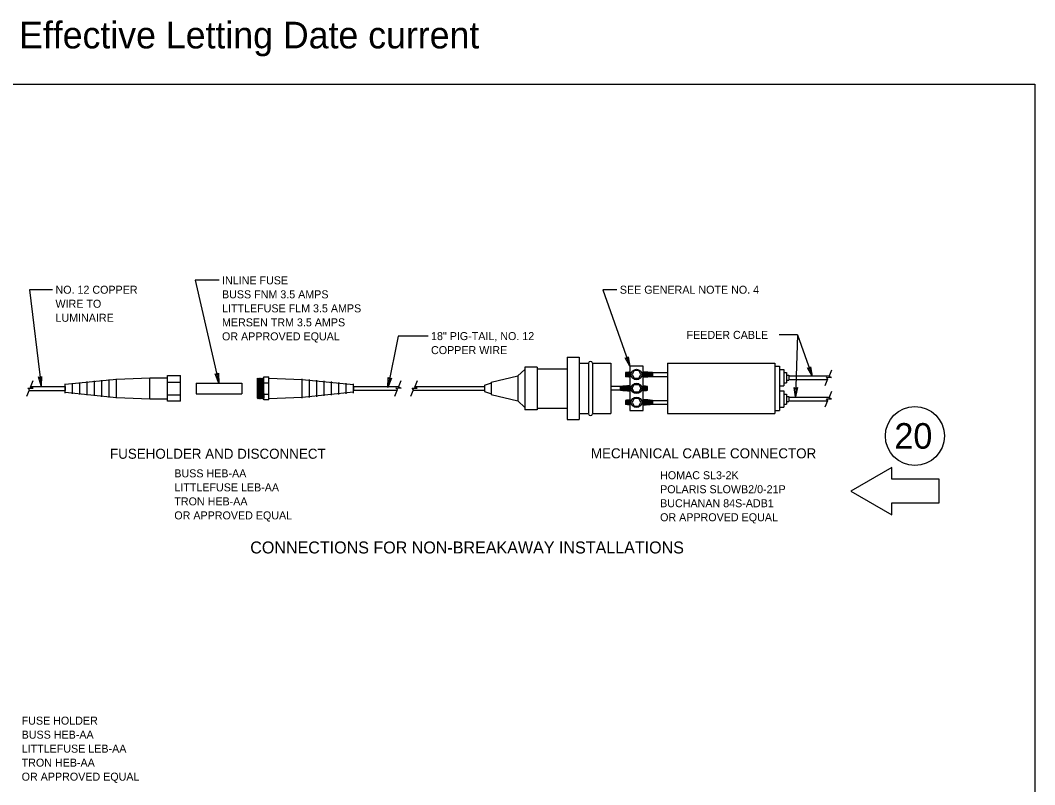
# Model space of a CAD drawing. Extents: x 99981 to 128681, y 99783 to 102182.
# Drawn here: x 127161 to 128681, y 101036 to 102182 of the extents above; entities that cross this region are included whole.
import ezdxf

# ---------------------------------------------------------------- set-up
doc = ezdxf.new("R2010")
doc.units = 0
for name, color, linetype in [('Default', 7, 'Continuous'), ('Level 1', 7, 'Continuous'), ('RD Lighting', 7, 'Continuous'), ('RD Standard Plans Active', 7, 'Continuous')]:
    doc.layers.add(name, color=color, linetype=linetype)

msp = doc.modelspace()

# ---------------------------------------------------------------- linework, layer by layer
at = {"layer": 'Default'}
msp.add_lwpolyline([(125481.4, 102086.3), (128681.1, 102086.3), (128681.1, 99886.7), (125481.4, 99886.7)], close=True, dxfattribs=at)
at = {"layer": 'Level 1'}
for p, q in [((127422.6, 101792.3), (127458.4, 101638.1)), ((127458.5, 101792.3), (127422.6, 101792.3)), ((127208.9, 101778.2), (127174.4, 101778.2)), ((127174.4, 101778.2), (127191.8, 101633.9)), ((128033.6, 101778.2), (128074.1, 101663.4)), ((128054.8, 101778.2), (128033.6, 101778.2)), ((127727, 101708.7), (127711.7, 101631.6)), ((127771.8, 101708.7), (127727, 101708.7)), ((128325.5, 101710.5), (128298, 101710.5)), ((128325.5, 101710.5), (128322.4, 101617.7)), ((128325.5, 101710.5), (128347.3, 101648.6)), ((127980.4, 101677), (127980.4, 101583.6)), ((127980.4, 101677), (127998.2, 101677)), ((127998.2, 101677), (127998.2, 101583.6)), ((127906.1, 101648.9), (127916.7, 101658.5)), ((127916.6, 101662.3), (127916.6, 101598.3)), ((127935.3, 101662.3), (127916.6, 101662.3)), ((127935.3, 101662.3), (127935.3, 101598.3)), ((127935.3, 101659.8), (127980.1, 101659.8)), ((127998.2, 101668.2), (128012.4, 101668.2)), ((128012.4, 101668.2), (128012.4, 101592.5)), ((128018.5, 101668.2), (128018.5, 101592.5)), ((128018.5, 101668.2), (128045.5, 101668.2)), ((128045.5, 101668.2), (128045.5, 101592.5)), ((128130.9, 101668.2), (128291.7, 101668.2)), ((128130.9, 101668.2), (128130.9, 101592.5)), ((128291.7, 101668.2), (128291.7, 101592.5)), ((128291.7, 101663.4), (128298.3, 101663.4)), ((128298.3, 101663.4), (128298.3, 101597.2)), ((128298.3, 101658.7), (128305, 101658.7)), ((128305, 101658.7), (128305, 101634.1)), ((128372.8, 101648.3), (128376.9, 101658.1)), ((127176.1, 101632.2), (127180.1, 101641.9)), ((127304.7, 101643.6), (127227.9, 101635.9)), ((127282.7, 101617.8), (127282.7, 101642.6)), ((127293.7, 101616.7), (127293.7, 101643.6)), ((127354.6, 101645.5), (127304.7, 101643.6)), ((127304.7, 101615.6), (127304.7, 101644.8)), ((127354.6, 101614.8), (127354.6, 101645.5)), ((127381.5, 101645.5), (127354.6, 101645.5)), ((127381.5, 101611), (127381.5, 101649.4)), ((127381.5, 101649.4), (127400.7, 101649.4)), ((127400.7, 101611), (127400.7, 101649.4)), ((127516.1, 101615.8), (127516.1, 101645.5)), ((127517, 101644.6), (127516.1, 101645.5)), ((127516.1, 101642.9), (127517, 101614.8)), ((127517.9, 101645.5), (127517, 101644.6)), ((127517, 101644.6), (127517.9, 101615.8)), ((127517.9, 101645.5), (127518.9, 101614.8)), ((127518.9, 101644.6), (127517.9, 101645.5)), ((127519.9, 101645.5), (127518.9, 101644.6)), ((127518.9, 101644.6), (127519.8, 101615.8)), ((127519.9, 101645.5), (127520.8, 101614.8)), ((127520.9, 101644.6), (127519.9, 101645.5)), ((127521.8, 101645.5), (127520.9, 101644.6)), ((127520.9, 101644.6), (127521.8, 101615.8)), ((127521.8, 101645.5), (127522.7, 101614.8)), ((127522.8, 101644.6), (127521.8, 101645.5)), ((127523.7, 101645.5), (127522.8, 101644.6)), ((127522.8, 101644.6), (127523.7, 101615.8)), ((127523.7, 101645.5), (127524.7, 101614.8)), ((127524.7, 101644.6), (127523.7, 101645.5)), ((127525.6, 101645.5), (127524.7, 101644.6)), ((127524.7, 101644.6), (127525.6, 101615.8)), ((127525.6, 101612.9), (127525.6, 101647.5)), ((127525.6, 101647.5), (127533.3, 101647.5)), ((127533.3, 101612.9), (127533.3, 101647.5)), ((127533.3, 101614.8), (127533.3, 101645.5)), ((127533.3, 101645.5), (127583.2, 101643.6)), ((127583.2, 101615.6), (127583.2, 101644.8)), ((127583.2, 101643.6), (127660, 101636)), ((127594.2, 101616.7), (127594.2, 101643.7)), ((127605.2, 101617.8), (127605.2, 101642.6)), ((127616.2, 101618.9), (127616.2, 101641.5)), ((127727.5, 101632.2), (127731.5, 101642)), ((127751.8, 101632.1), (127755.9, 101641.9)), ((127866.6, 101639.4), (127906.1, 101648.9)), ((127906.1, 101648.9), (127906.1, 101611.7)), ((128067.5, 101654), (128067.5, 101648.3)), ((128108.2, 101654), (128108.2, 101648.3)), ((128108.2, 101654), (128131, 101654)), ((128108.2, 101648.3), (128131, 101648.3)), ((128305, 101654), (128308.8, 101654)), ((128308.8, 101654), (128308.8, 101638.8)), ((128308.8, 101650.2), (128312.5, 101650.2)), ((128308.8, 101642.6), (128312.5, 101642.6)), ((128312.5, 101650.2), (128312.5, 101642.6)), ((128312.5, 101649.2), (128373.2, 101649.2)), ((128312.5, 101643.6), (128370.8, 101643.6)), ((128367.2, 101634.8), (128371.2, 101644.5)), ((128371.2, 101644.5), (128368.8, 101647)), ((128368.8, 101647), (128376.7, 101646.6)), ((128376.7, 101646.6), (128372.8, 101648.3)), ((127170.4, 101618.6), (127174.4, 101628.3)), ((127174.4, 101628.3), (127172, 101630.8)), ((127172, 101630.8), (127179.9, 101630.5)), ((127174, 101627.3), (127227.9, 101627.3)), ((127179.9, 101630.5), (127176.1, 101632.2)), ((127176.4, 101633), (127227.9, 101633)), ((127227.9, 101623.3), (127227.9, 101637.1)), ((127227.9, 101633), (127227.9, 101627.3)), ((127227.9, 101627.3), (127227.9, 101633)), ((127238.8, 101622.1), (127238.8, 101638.2)), ((127249.8, 101621.1), (127249.8, 101639.3)), ((127260.8, 101620), (127260.8, 101640.4)), ((127271.7, 101618.9), (127271.7, 101641.5)), ((127381.5, 101639.8), (127400.7, 101639.8)), ((127424.3, 101638.1), (127492.5, 101638.1)), ((127424.3, 101638.1), (127424.3, 101622.2)), ((127492.5, 101638.1), (127492.5, 101622.2)), ((127525.6, 101638.8), (127533.3, 101638.8)), ((127627.1, 101620), (127627.1, 101640.4)), ((127638.1, 101621.1), (127638.1, 101639.3)), ((127649.1, 101622.2), (127649.1, 101638.2)), ((127660, 101623.3), (127660, 101637.1)), ((127660, 101633), (127660, 101627.4)), ((127660, 101633), (127727.8, 101633)), ((127660, 101627.4), (127725.4, 101627.4)), ((127721.8, 101618.7), (127725.9, 101628.4)), ((127725.9, 101628.4), (127723.4, 101630.9)), ((127723.4, 101630.9), (127731.3, 101630.5)), ((127731.3, 101630.5), (127727.5, 101632.2)), ((127746.2, 101618.6), (127750.2, 101628.3)), ((127750.2, 101628.3), (127747.8, 101630.8)), ((127747.8, 101630.8), (127755.7, 101630.4)), ((127749.8, 101627.4), (127856.2, 101627.4)), ((127755.7, 101630.4), (127751.8, 101632.1)), ((127752.2, 101633), (127856.2, 101633)), ((127856.2, 101634.9), (127866.8, 101638.6)), ((127856.2, 101634.9), (127856.2, 101625.7)), ((127866.6, 101639.4), (127866.6, 101621.2)), ((128060.2, 101633.1), (128045.5, 101633.1)), ((128060.2, 101627.5), (128045.5, 101627.5)), ((128060.2, 101627.5), (128060.2, 101633.1)), ((128100.9, 101627.5), (128100.9, 101633.1)), ((128298.3, 101634.1), (128305, 101634.1)), ((128298.3, 101626.5), (128305, 101626.5)), ((128305, 101638.8), (128308.8, 101638.8)), ((128305, 101626.5), (128305, 101601.9)), ((127227.9, 101624.4), (127304.7, 101616.7)), ((127304.7, 101616.7), (127354.6, 101614.8)), ((127354.6, 101614.8), (127381.5, 101614.8)), ((127381.5, 101620.6), (127400.7, 101620.6)), ((127424.3, 101622.2), (127492.5, 101622.2)), ((127516.1, 101615.8), (127517, 101614.8)), ((127517, 101614.8), (127517.9, 101615.8)), ((127517.9, 101615.8), (127518.9, 101614.8)), ((127518.9, 101614.8), (127519.8, 101615.8)), ((127519.8, 101615.8), (127520.8, 101614.8)), ((127520.8, 101614.8), (127521.8, 101615.8)), ((127521.8, 101615.8), (127522.7, 101614.8)), ((127522.7, 101614.8), (127523.7, 101615.8)), ((127523.7, 101615.8), (127524.7, 101614.8)), ((127524.7, 101614.8), (127525.6, 101615.8)), ((127525.6, 101621.5), (127533.3, 101621.5)), ((127533.3, 101612.9), (127525.6, 101612.9)), ((127583.2, 101616.8), (127533.3, 101614.8)), ((127660, 101624.4), (127583.2, 101616.8)), ((127856.2, 101625.7), (127866.8, 101622)), ((127866.6, 101621.2), (127906.1, 101611.7)), ((127906.1, 101611.7), (127916.7, 101601.7)), ((128067.5, 101612.3), (128067.5, 101606.7)), ((128108.2, 101612.3), (128108.2, 101606.7)), ((128108.2, 101612.3), (128131, 101612.3)), ((128305, 101621.8), (128308.8, 101621.8)), ((128308.8, 101621.8), (128308.8, 101606.7)), ((128308.8, 101618), (128312.5, 101618)), ((128312.5, 101618), (128312.5, 101610.4)), ((128312.5, 101617.1), (128373.2, 101617.1)), ((128312.5, 101611.4), (128370.8, 101611.4)), ((128367.2, 101602.6), (128371.2, 101612.3)), ((128371.2, 101612.3), (128368.8, 101614.8)), ((128368.8, 101614.8), (128376.7, 101614.5)), ((128372.8, 101616.2), (128376.9, 101625.9)), ((128376.7, 101614.5), (128372.8, 101616.2)), ((127400.7, 101611), (127381.5, 101611)), ((127935.3, 101598.3), (127916.6, 101598.3)), ((127935.3, 101600.8), (127980.1, 101600.8)), ((128108.2, 101606.7), (128131, 101606.7)), ((128291.7, 101597.2), (128298.3, 101597.2)), ((128298.3, 101601.9), (128305, 101601.9)), ((128305, 101606.7), (128308.8, 101606.7)), ((128308.8, 101610.4), (128312.5, 101610.4)), ((127980.4, 101583.6), (127998.2, 101583.6)), ((127998.2, 101592.5), (128012.4, 101592.5)), ((128018.5, 101592.5), (128045.5, 101592.5)), ((128130.9, 101592.5), (128291.7, 101592.5))]:
    msp.add_line(p, q, dxfattribs=at)
for points in [[(128071.7, 101677.5), (128074.1, 101663.4), (128067.2, 101675.9), (128070.2, 101674.6)], [(128074.1, 101597.2), (128094.3, 101597.2), (128094.3, 101663.4), (128074.1, 101663.4)], [(128090.8, 101651.1), (128087.5, 101656.9), (128080.9, 101656.9), (128077.6, 101651.1), (128080.9, 101645.4), (128087.5, 101645.4)], [(128344.9, 101662.7), (128347.3, 101648.6), (128340.4, 101661.1), (128343.4, 101659.8)], [(127192.5, 101648.2), (127191.8, 101633.9), (127187.7, 101647.6), (127190.4, 101645.7)], [(127457.5, 101653.2), (127458.4, 101638.1), (127452.6, 101652.1), (127455.6, 101650.4)], [(127717.1, 101645.8), (127711.7, 101631.6), (127712.2, 101646.7), (127714.2, 101644)], [(128077.6, 101630.3), (128080.9, 101636), (128087.5, 101636), (128090.8, 101630.3), (128087.5, 101624.6), (128080.9, 101624.6)], [(128325.3, 101631.7), (128322.4, 101617.7), (128320.5, 101631.8), (128322.8, 101629.6)], [(128090.8, 101609.5), (128087.5, 101615.2), (128080.9, 101615.2), (128077.6, 101609.5), (128080.9, 101603.8), (128087.5, 101603.8)]]:
    msp.add_lwpolyline(points, close=True, dxfattribs=at)
for centre in [(128084.2, 101651.1), (128084.2, 101630.3), (128084.2, 101609.5)]:
    msp.add_circle(centre, 7.87, dxfattribs=at)
for centre, radius, start, end in [((128015.4, 101667.4), 3.13, 13.8187, 166.1813), ((128081.3, 101681.3), 35.3, 246.9234, 250.0588), ((128087.9, 101472.5), 182.6, 94.3078, 96.3947), ((128087.9, 101829.8), 182.6, 263.6053, 265.6922), ((128081.3, 101681.3), 31.3, 244.0184, 256.695), ((128081.3, 101681.3), 32.1, 244.8289, 257.172), ((128081.3, 101681.3), 32.9, 245.3688, 257.4424), ((128081.3, 101681.3), 33.5, 245.8941, 257.5753), ((128081.3, 101681.3), 34.2, 246.2968, 257.7799), ((128081.3, 101681.3), 34.8, 246.798, 253.7631), ((128081.3, 101681.3), 30.6, 243.617, 256.3872), ((128081.3, 101681.3), 30, 245.4513, 256.2262), ((128081.3, 101681.3), 29.3, 247.3871, 255.8534), ((128081.3, 101681.3), 28.7, 249.6525, 255.6032), ((128108, 101681.1), 34.2, 246.2968, 258.5078), ((128087.9, 101472.5), 182.6, 83.6053, 87.9783), ((128108, 101681.1), 31.9, 244.725, 270.432), ((128108, 101681.1), 33.4, 245.9109, 263.6185), ((128108, 101681.1), 34.8, 246.8841, 255.1625), ((128108, 101681.1), 35.4, 247.2896, 252.3204), ((128087.9, 101829.8), 182.6, 272.0217, 276.3947), ((128108, 101681.1), 36, 247.6656, 249.8244), ((128108, 101681.1), 30.1, 243.205, 270.432), ((128108, 101681.1), 32.8, 245.5356, 270.432), ((128108, 101681.1), 31, 244.1545, 270.432), ((128108, 101681.1), 29.2, 244.3604, 270.432), ((128108, 101681.1), 28.5, 246.8058, 270.432), ((128108, 101681.1), 27.9, 250.4487, 270.432), ((128108, 101681.1), 27.2, 257.6483, 270.432), ((128080.6, 101451.7), 182.6, 92.0217, 96.3947), ((128060.5, 101600.3), 32.8, 65.5356, 90.432), ((128060.5, 101600.3), 31.9, 64.725, 90.432), ((128080.6, 101809), 182.6, 263.6053, 267.9783), ((128060.5, 101600.3), 31, 64.1545, 90.432), ((128060.5, 101600.3), 30.1, 63.205, 90.432), ((128060.5, 101600.3), 29.2, 64.3604, 90.432), ((128060.5, 101600.3), 28.5, 66.8058, 90.432), ((128060.5, 101600.3), 27.9, 70.4487, 90.432), ((128060.5, 101600.3), 27.2, 77.6484, 90.432), ((128060.5, 101600.3), 33.4, 65.9109, 83.6185), ((128060.5, 101600.3), 34.2, 66.2968, 78.5078), ((128060.5, 101600.3), 34.8, 66.8841, 75.1625), ((128060.5, 101600.3), 35.4, 67.2896, 72.3204), ((128060.5, 101600.3), 36, 67.6656, 69.8244), ((128080.6, 101451.7), 182.6, 83.6053, 85.6922), ((128087.1, 101600.1), 33.5, 65.8941, 77.5753), ((128087.1, 101600.1), 32.9, 65.3688, 77.4424), ((128087.1, 101600.1), 32.1, 64.8289, 77.172), ((128087.1, 101600.1), 31.3, 64.0184, 76.695), ((128087.1, 101600.1), 30.6, 63.617, 76.3872), ((128087.1, 101600.1), 30, 65.4513, 76.2262), ((128087.1, 101600.1), 29.3, 67.3871, 75.8534), ((128087.1, 101600.1), 28.7, 69.6525, 75.6032), ((128080.6, 101809), 182.6, 274.3078, 276.3947), ((128087.1, 101600.1), 34.2, 66.2968, 77.7799), ((128087.1, 101600.1), 34.8, 66.798, 73.7631), ((128087.1, 101600.1), 35.3, 66.9234, 70.0588), ((128087.9, 101430.9), 182.6, 94.3078, 96.3947), ((128081.3, 101639.7), 31.3, 244.0184, 256.695), ((128081.3, 101639.7), 30.6, 243.617, 256.3872), ((128081.3, 101639.7), 30, 245.4513, 256.2262), ((128081.3, 101639.7), 29.3, 247.3871, 255.8534), ((128081.3, 101639.7), 28.7, 249.6525, 255.6032), ((128087.9, 101430.9), 182.6, 83.6053, 87.9783), ((128108, 101639.5), 30.1, 243.205, 270.432), ((128108, 101639.5), 31, 244.1545, 270.432), ((128108, 101639.5), 29.2, 244.3604, 270.432), ((128108, 101639.5), 28.5, 246.8058, 270.432), ((128108, 101639.5), 27.9, 250.4487, 270.432), ((128108, 101639.5), 27.2, 257.6483, 270.432), ((128081.3, 101639.7), 35.3, 246.9234, 250.0588), ((128087.9, 101788.1), 182.6, 263.6053, 265.6922), ((128081.3, 101639.7), 32.1, 244.8289, 257.172), ((128081.3, 101639.7), 32.9, 245.3688, 257.4424), ((128081.3, 101639.7), 33.5, 245.8941, 257.5753), ((128081.3, 101639.7), 34.2, 246.2968, 257.7799), ((128081.3, 101639.7), 34.8, 246.798, 253.7631), ((128108, 101639.5), 34.2, 246.2968, 258.5078), ((128108, 101639.5), 31.9, 244.725, 270.432), ((128108, 101639.5), 33.4, 245.9109, 263.6185), ((128108, 101639.5), 34.8, 246.8841, 255.1625), ((128108, 101639.5), 35.4, 247.2896, 252.3204), ((128087.9, 101788.1), 182.6, 272.0217, 276.3947), ((128108, 101639.5), 36, 247.6656, 249.8244), ((128108, 101639.5), 32.8, 245.5356, 270.432), ((128015.4, 101592.8), 3.13, 193.8187, 346.1813)]:
    msp.add_arc(centre, radius, start, end, dxfattribs=at)
at = {"layer": 'RD Lighting'}
msp.add_lwpolyline([(128405.6, 101476.2), (128467, 101440.8), (128467, 101458.5), (128538, 101458.5), (128538, 101494), (128467, 101494), (128467, 101511.7)], close=True, dxfattribs=at)
msp.add_circle((128501.4, 101559), 44.2, dxfattribs=at)

# ---------------------------------------------------------------- texts
at = {"layer": 'Level 1'}
for s, height, p in [(' INLINE FUSE', 12, (127458.5, 101786.3)), (' NO. 12 COPPER ', 12, (127208.9, 101772.2)), (' SEE GENERAL NOTE NO. 4', 12, (128054.8, 101772.2)), (' WIRE TO ', 12, (127208.9, 101751.2)), (' BUSS FNM 3.5 AMPS', 12, (127458.5, 101765.3)), (' LITTLEFUSE FLM 3.5 AMPS', 12, (127458.5, 101744.3)), (' LUMINAIRE', 12, (127208.9, 101730.2)), (' MERSEN TRM 3.5 AMPS ', 12, (127458.5, 101723.3)), (' OR APPROVED EQUAL', 12, (127458.5, 101702.3)), (' 18" PIG-TAIL, NO. 12', 12, (127771.8, 101702.7)), ('FEEDER CABLE ', 12, (128159.3, 101704.5)), (' COPPER WIRE', 12, (127771.8, 101681.7)), ('FUSEHOLDER AND DISCONNECT', 15, (127295.1, 101524.8)), ('MECHANICAL CABLE CONNECTOR', 15, (128015.9, 101525.4)), ('BUSS HEB-AA', 12, (127391.5, 101496.9)), ('HOMAC SL3-2K', 12, (128119.6, 101494.1)), ('LITTLEFUSE LEB-AA', 12, (127391.5, 101475.9)), ('POLARIS SLOWB2/0-21P', 12, (128119.6, 101473.1)), ('TRON HEB-AA', 12, (127391.5, 101454.9)), ('BUCHANAN 84S-ADB1', 12, (128119.6, 101452.1)), ('OR APPROVED EQUAL', 12, (127391.5, 101433.9)), ('OR APPROVED EQUAL', 12, (128119.6, 101431.1)), ('CONNECTIONS FOR NON-BREAKAWAY INSTALLATIONS', 18, (127505.3, 101382.8)), (' FUSE HOLDER', 12, (127158.2, 101126.2)), (' BUSS HEB-AA', 12, (127158.2, 101105.2)), (' LITTLEFUSE LEB-AA', 12, (127158.2, 101084.2)), (' TRON HEB-AA ', 12, (127158.2, 101063.2)), (' OR APPROVED EQUAL', 12, (127158.2, 101042.2))]:
    msp.add_text(s, height=height, dxfattribs=at).set_placement(p)
at = {"layer": 'RD Lighting'}
msp.add_text('20', height=38.31, dxfattribs=at).set_placement((128470.7, 101539.9))
at = {"layer": 'RD Standard Plans Active'}
msp.add_text('Effective Letting Date current', height=40, dxfattribs=at).set_placement((127158.8, 102140))

doc.saveas('drawing.dxf')
